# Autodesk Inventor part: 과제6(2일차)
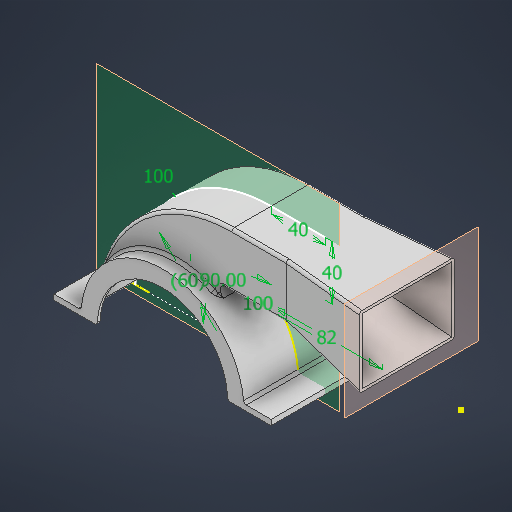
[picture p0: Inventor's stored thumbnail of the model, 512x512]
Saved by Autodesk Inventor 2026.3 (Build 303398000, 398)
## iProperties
Created: 2026-08
Part Number: 과제6(2일차)
Material: 일반
Document SubType Name: Modeling
Designer: chang
Density: 1 g/cm^3
Appearance: 기본값
Author: chang
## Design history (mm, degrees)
sketch "스케치1"
  geometry: L1 (-60, 0)-(-80, 0); L2 (-80, 0)-(-80, 4); L3 (-80, 4)-(-61.709, 4) reference; L4 (60, 0)-(80, 0); L5 (80, 0)-(80, 4); L6 (80, 4)-(61.709, 4); L7 (-60, 0)-(-49.96, 0); L8 (49.96, 0)-(60, 0); A1 r 48 centre (0, 0) between (47.962, 1.92) and (-47.962, 1.92); A2 r 60 centre (0, 0) between (59.718, 5.806) and (-59.718, 5.806); A3 r 2 centre (-61.709, 6) between (-61.709, 4) and (-59.718, 5.806); A4 r 2 centre (-49.96, 2) between (-49.96, 0) and (-47.962, 1.92); A5 r 2 centre (49.96, 2) between (47.962, 1.92) and (49.96, 0); A6 r 2 centre (61.709, 6) between (59.718, 5.806) and (61.709, 4); 5 further points
  constraints: 16 end point, 16 point on circle, 8 tangent, 7 point on line, 6 centre point, 3 equal radius, 3 horizontal, 2 coincident, 2 perpendicular, 1 collinear, 1 parallel
  dimensions: "d0" = 48 radius of A1; "d1" = 60 radius of A2; "d2" = 20 distance of L1.start L1.end; "d3" = 4 distance of L1.end L2.end; "d4" = 20 distance of L4.start L4.end; "d5" = 4 distance of L4.end L5.end; "d6" = 80 distance from line of point (0, 0) L5; "d7" = 80 distance from line of point (0, 0) L2; "d8" = 2 radius of A3 (derived)
extrude "돌출1" new body sketch "스케치1" distance "d9" = 80; taper "d10" = 0 deg
sketch "스케치4"
  geometry: 1 further point
sketch "스케치5"
  geometry: 1 further point
sketch "스케치20"
  geometry: L1 (0, 0)-(-82, 0)
  constraints: 2 end point, 1 horizontal
  dimensions: "d44" = 82 distance of L1.start L1.end
sketch "스케치21"
  geometry: L1 (59.718, 0)-(-40.282, 0); 1 further point
  constraints: 2 end point, 1 horizontal
  dimensions: "d45" = 100 distance of L1.start L1.end
sketch "스케치22"
  geometry: 1 further point
sketch "스케치23"
  geometry: 1 further point
sketch "스케치25"
  geometry: 1 further point
node "작업 평면2"
sketch "스케치26"
  geometry: 1 further point
sketch "스케치27"
  geometry: 1 further point
sketch "스케치28"
  geometry: 1 further point
sketch "스케치29"
  geometry: L1 (80, 0)-(49.96, 0) reference; L2 (-40, 0)-(-40, 100); L3 (-40, 0)-(60, 0); L4 (-40, 100)-(-80, 100); L5 (-80, 100)-(-80, 60) reference; L6 (-80, 60)-(-40, 60); L7 (-40, 60)-(0, 60) reference; A1 r 100 centre (-40, 0) between (60, 0) and (-40, 100); A2 r 60 centre (0, 0) between (60, 0) and (0, 60); 1 further point
  constraints: 12 end point, 4 point on circle, 3 point on line, 2 centre point, 2 horizontal, 2 perpendicular, 1 coincident, 1 vertical
  dimensions: "d50" = 100 radius of A1; "d51" = 90 deg angle of L3 L2; "d52" = 40 distance of L2.end L4.end; "d53" = 40 distance of L4.end L5.end
sketch "스케치30"
  geometry: 1 further point
sketch "스케치31"
  geometry: L1 (80, 0)-(49.96, 0) reference; A1 r 60 centre (0, 0) between (59.718, 5.806) and (-59.718, 5.806) reference; A2 r 60 centre (0, 0) between (60, 0) and (0, 60); 1 further point
  constraints: 3 point on circle, 1 centre point, 1 coincident, 1 point on line
  dimensions: "d54" = 60 radius of A2 (derived)
extrude "돌출4" join sketch "스케치29" stored distance "d55" = 58; taper "d56" = 0 deg
fillet "모깎기1" dims "d57" = 5
node "작업 평면3"
sketch "스케치32"
  geometry: 1 further point
sketch "스케치33"
  geometry: 1 further point
sketch "스케치34"
  geometry: L1 (-58, 40)-(0, 40) reference; L2 (-58, 40)-(0, 40); L3 (-64, 40)-(6, 40); L4 (6, 40)-(6, -12); L5 (6, -12)-(-64, -12); L6 (-69, -12)-(11, -12) reference; L7 (-64, -12)-(-64, 40); 2 further points
  constraints: 10 end point, 2 midpoint, 1 collinear, 1 horizontal, 1 perpendicular, 1 point on line
  dimensions: "d59" = 70 distance of L3.start L3.end; "d60" = 52 distance of L3.end L4.end; "d61" = 70 distance of L4.end L5.end
sketch "스케치35"
  geometry: 1 further point
feature "로프트1" dims "d62" = 0, "d63" = 90 deg, "d64" = 0, "d65" = 90 deg
  node "모서리1"
feature "쉘1" dims "d66" = 2
feature "면 모깎기1" dims "d67" = 2
feature "면 모깎기2" dims "d68" = 2
feature "면 모깎기3" dims "d69" = 2
feature "면 모깎기4" dims "d70" = 2
feature "면 모깎기5" dims "d71" = 2
feature "면 모깎기6" dims "d72" = 2
feature "면 모깎기7" dims "d73" = 2
feature "면 모깎기8" dims "d74" = 2
feature "면 모깎기9" dims "d75" = 2
sketch "스케치36"
  geometry: 1 further point
sketch "스케치37"
  geometry: 1 further point
feature "면 모깎기10" dims "d76" = 3.25
node "솔리드1"
